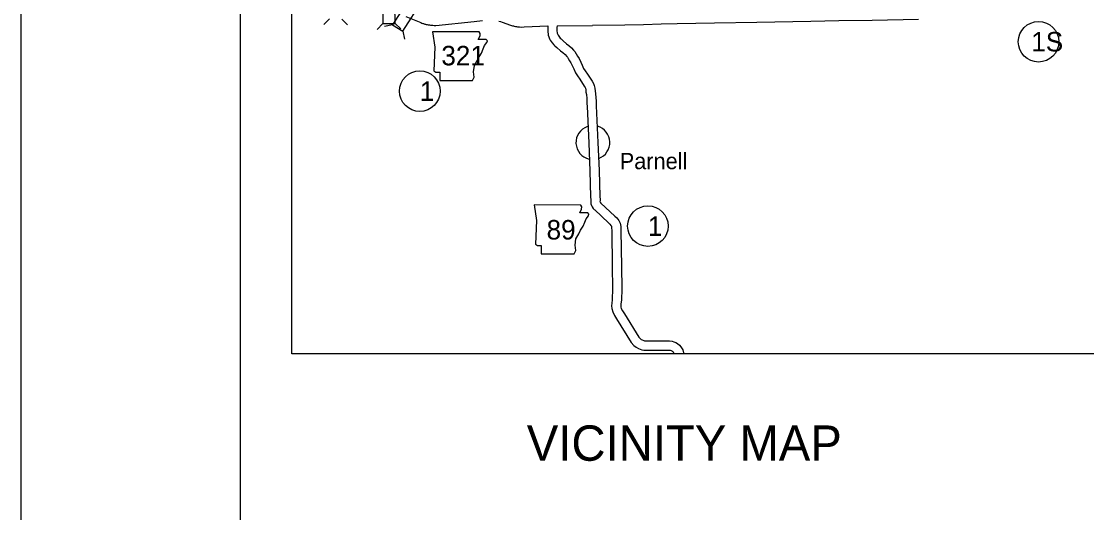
# Model space of a CAD drawing. Extents: x 1367863 to 1368197, y 380048 to 380261.
# Drawn here: x 1367863.4 to 1367923.7, y 380178.5 to 380206.3 of the extents above; entities that cross this region are included whole.
import ezdxf

# ---------------------------------------------------------------- set-up
doc = ezdxf.new("R2010")
doc.units = 0
for name, color, linetype in [('Level 10', 7, 'Continuous'), ('Level 20', 7, 'Continuous'), ('Level 21', 7, 'Continuous'), ('Level 24', 7, 'Continuous'), ('Level 27', 7, 'Continuous'), ('R_Border', 7, 'Continuous'), ('R_Dimension', 7, 'Continuous'), ('R_No Plot', 7, 'Continuous')]:
    doc.layers.add(name, color=color, linetype=linetype)

msp = doc.modelspace()

# ---------------------------------------------------------------- linework, layer by layer
at = {"layer": 'Level 10'}
for points in [[(1367885.15, 380206.595), (1367886.004, 380206.243), (1367886.071, 380206.219), (1367886.124, 380206.199), (1367886.155, 380206.188), (1367886.199, 380206.172), (1367886.232, 380206.163), (1367886.272, 380206.15), (1367886.316, 380206.141), (1367886.362, 380206.129), (1367886.422, 380206.118), (1367886.461, 380206.114), (1367886.494, 380206.111), (1367886.547, 380206.105), (1367886.604, 380206.101), (1367886.679, 380206.094), (1367886.771, 380206.086), (1367886.858, 380206.086), (1367889.021, 380206.312), (1367889.505, 380206.363)], [(1367890.423, 380206.335), (1367890.523, 380206.31), (1367890.618, 380206.274), (1367891.082, 380206.102), (1367891.141, 380206.084), (1367891.19, 380206.069), (1367891.244, 380206.057), (1367891.3, 380206.043), (1367891.364, 380206.029), (1367891.42, 380206.02), (1367891.489, 380206.009), (1367891.551, 380206.004), (1367891.6, 380206.001), (1367891.681, 380205.993), (1367891.858, 380205.997), (1367893.195, 380206.056)], [(1367914.174, 380206.415), (1367911.551, 380206.359), (1367909.672, 380206.337), (1367908.092, 380206.316), (1367905.035, 380206.258), (1367902.632, 380206.209), (1367900.518, 380206.174), (1367899.608, 380206.159), (1367898.619, 380206.126), (1367897.551, 380206.107), (1367895.732, 380206.073)], [(1367893.195, 380206.056), (1367893.188, 380205.831), (1367893.195, 380205.707), (1367893.209, 380205.604), (1367893.221, 380205.539), (1367893.244, 380205.444), (1367893.288, 380205.332), (1367893.336, 380205.253), (1367893.384, 380205.178), (1367893.445, 380205.097), (1367893.532, 380204.996), (1367893.598, 380204.939), (1367893.704, 380204.834), (1367893.92, 380204.649), (1367894.049, 380204.547), (1367894.169, 380204.439), (1367894.268, 380204.329), (1367894.306, 380204.287), (1367894.354, 380204.212), (1367894.43, 380204.082), (1367894.498, 380203.965), (1367894.585, 380203.776), (1367894.66, 380203.622), (1367894.759, 380203.399), (1367894.874, 380203.23), (1367895.005, 380203.036), (1367895.262, 380202.648), (1367895.304, 380202.58), (1367895.321, 380202.534), (1367895.342, 380202.442), (1367895.356, 380202.306), (1367895.377, 380202.168), (1367895.395, 380201.955), (1367895.404, 380201.798), (1367895.411, 380201.64), (1367895.419, 380201.514), (1367895.509, 380199.428), (1367895.578, 380197.862), (1367895.616, 380196.373), (1367895.629, 380196.218), (1367895.629, 380196.183), (1367895.624, 380196.107), (1367895.631, 380196.035), (1367895.639, 380195.988), (1367895.671, 380195.882), (1367895.714, 380195.821), (1367895.764, 380195.729), (1367895.844, 380195.649)], [(1367893.716, 380206.069), (1367893.715, 380205.967), (1367893.711, 380205.837), (1367893.715, 380205.758), (1367893.725, 380205.688), (1367893.733, 380205.648), (1367893.744, 380205.601), (1367893.758, 380205.564), (1367893.779, 380205.529), (1367893.813, 380205.477), (1367893.853, 380205.424), (1367893.901, 380205.367), (1367893.952, 380205.324), (1367894.059, 380205.218), (1367894.253, 380205.052), (1367894.386, 380204.946), (1367894.539, 380204.809), (1367894.657, 380204.678), (1367894.722, 380204.604), (1367894.799, 380204.486), (1367894.882, 380204.344), (1367894.962, 380204.205), (1367895.057, 380204), (1367895.134, 380203.843), (1367895.217, 380203.654), (1367895.306, 380203.524), (1367895.44, 380203.326), (1367895.703, 380202.928), (1367895.776, 380202.807), (1367895.822, 380202.683), (1367895.858, 380202.528), (1367895.874, 380202.373), (1367895.896, 380202.229), (1367895.916, 380201.992), (1367895.926, 380201.825), (1367895.933, 380201.666), (1367895.94, 380201.541), (1367896.03, 380199.451), (1367896.1, 380197.88), (1367896.138, 380196.402), (1367896.152, 380196.237), (1367896.151, 380196.163), (1367896.148, 380196.117), (1367896.148, 380196.111), (1367896.157, 380196.098), (1367896.186, 380196.046), (1367896.213, 380196.019)], [(1367893.716, 380206.069), (1367895.728, 380206.073)], [(1367896.206, 380196.025), (1367896.994, 380195.293), (1367897.105, 380195.184), (1367897.216, 380195.042), (1367897.291, 380194.888), (1367897.331, 380194.706), (1367897.337, 380194.464), (1367897.367, 380192.444), (1367897.377, 380191.18), (1367897.359, 380190.524), (1367897.337, 380190.316), (1367897.333, 380190.207), (1367897.334, 380190.137), (1367897.355, 380190.06), (1367897.429, 380189.921), (1367897.533, 380189.752), (1367898.341, 380188.44), (1367898.416, 380188.352), (1367898.475, 380188.309), (1367898.531, 380188.278), (1367898.625, 380188.248), (1367898.66, 380188.231), (1367898.673, 380188.23), (1367898.852, 380188.22), (1367898.973, 380188.222), (1367900.076, 380188.229), (1367900.226, 380188.212), (1367900.338, 380188.177), (1367900.442, 380188.139), (1367900.545, 380188.073), (1367900.653, 380187.986), (1367900.721, 380187.894), (1367900.77, 380187.823), (1367900.836, 380187.71), (1367900.877, 380187.548), (1367900.88, 380187.495)], [(1367895.851, 380195.643), (1367896.633, 380194.916), (1367896.714, 380194.836), (1367896.77, 380194.763), (1367896.795, 380194.714), (1367896.81, 380194.643), (1367896.814, 380194.454), (1367896.845, 380192.438), (1367896.854, 380191.185), (1367896.837, 380190.558), (1367896.816, 380190.353), (1367896.81, 380190.214), (1367896.812, 380190.061), (1367896.868, 380189.865), (1367896.975, 380189.661), (1367897.089, 380189.477), (1367897.917, 380188.133), (1367898.059, 380187.966), (1367898.194, 380187.868), (1367898.322, 380187.796), (1367898.429, 380187.763), (1367898.513, 380187.721), (1367898.633, 380187.709), (1367898.843, 380187.698), (1367898.979, 380187.7), (1367900.048, 380187.706), (1367900.118, 380187.698), (1367900.171, 380187.682), (1367900.208, 380187.669), (1367900.239, 380187.648), (1367900.273, 380187.621), (1367900.296, 380187.59), (1367900.33, 380187.541), (1367900.348, 380187.511), (1367900.352, 380187.495)]]:
    msp.add_lwpolyline(points, dxfattribs=at)
at = {"layer": 'Level 20'}
for p, q in [((1367880.842, 380206.452), (1367880.512, 380206.132)), ((1367881.532, 380206.442), (1367881.852, 380206.112)), ((1367883.865, 380206.193), (1367883.545, 380205.863)), ((1367884.406, 380206.126), (1367883.957, 380206.026)), ((1367884.555, 380206.204), (1367884.885, 380205.884)), ((1367884.988, 380205.757), (1367885.088, 380205.308))]:
    msp.add_line(p, q, dxfattribs=at)
for points in [[(1367883.834, 380208.262), (1367883.865, 380206.193), (1367884.555, 380206.204), (1367884.523, 380208.272)], [(1367885.514, 380207.873), (1367884.406, 380206.126), (1367884.988, 380205.757), (1367886.096, 380207.504)]]:
    msp.add_lwpolyline(points, close=True, dxfattribs=at)
at = {"layer": 'Level 21'}
for points in [[(1367886.666, 380205.731), (1367886.798, 380204.848), (1367886.739, 380203.507), (1367886.857, 380203.434), (1367887.078, 380203.434), (1367887.078, 380202.962), (1367888.934, 380202.962), (1367889.022, 380203.154), (1367888.993, 380203.463), (1367889.037, 380203.816), (1367889.199, 380204.096), (1367889.302, 380204.303), (1367889.45, 380204.523), (1367889.538, 380204.759), (1367889.612, 380204.951), (1367889.744, 380205.113), (1367889.774, 380205.216), (1367889.715, 380205.289), (1367889.258, 380205.289), (1367889.361, 380205.496), (1367889.376, 380205.628), (1367889.315, 380205.73)], [(1367892.416, 380195.919), (1367892.548, 380195.035), (1367892.49, 380193.695), (1367892.607, 380193.621), (1367892.828, 380193.621), (1367892.828, 380193.15), (1367894.684, 380193.15), (1367894.773, 380193.341), (1367894.743, 380193.651), (1367894.787, 380194.004), (1367894.949, 380194.284), (1367895.052, 380194.49), (1367895.2, 380194.711), (1367895.288, 380194.947), (1367895.362, 380195.138), (1367895.494, 380195.3), (1367895.524, 380195.403), (1367895.465, 380195.477), (1367895.008, 380195.477), (1367895.111, 380195.683), (1367895.126, 380195.816), (1367895.065, 380195.918)]]:
    msp.add_lwpolyline(points, close=True, dxfattribs=at)
at = {"layer": 'Level 24'}
for start, end in [(109.01367, 256.82016), (290.4723, 73.95574)]:
    msp.add_arc((1367895.747, 380199.453), 0.958, start, end, dxfattribs=at)
at = {"layer": 'Level 27'}
for centre in [(1367920.975, 380205.164), (1367885.951, 380202.365), (1367898.863, 380194.725)]:
    msp.add_circle(centre, 1.149, dxfattribs=at)
at = {"layer": 'R_Border'}
msp.add_line((1367875.8, 380052.084), (1367875.8, 380257.536), dxfattribs=at)
at = {"layer": 'R_No Plot'}
for points in [[(1367863.393, 380261.431), (1368196.721, 380261.431), (1368196.721, 380048.101), (1367863.393, 380048.101)], [(1367878.711, 380254.093), (1367937.876, 380254.093), (1367937.876, 380187.495), (1367878.711, 380187.495)]]:
    msp.add_lwpolyline(points, close=True, dxfattribs=at)

# ---------------------------------------------------------------- texts
at = {"layer": 'Level 21'}
for s, p in [('321', (1367887.17, 380203.825)), ('89', (1367893.127, 380193.966))]:
    msp.add_text(s, height=1.1032, dxfattribs=at).set_placement(p)
at = {"layer": 'Level 24'}
msp.add_text('Parnell', height=0.9194, dxfattribs=at).set_placement((1367897.266, 380197.947))
at = {"layer": 'Level 27'}
for s, height, p in [('1S', 1.1032, (1367920.563, 380204.613)), ('1', 1.103, (1367885.951, 380201.813)), ('1', 1.103, (1367898.863, 380194.173))]:
    msp.add_text(s, height=height, dxfattribs=at).set_placement(p)
at = {"layer": 'R_Dimension'}
msp.add_text('VICINITY MAP', height=2, dxfattribs=at).set_placement((1367892.006, 380181.438))

doc.saveas('drawing.dxf')
